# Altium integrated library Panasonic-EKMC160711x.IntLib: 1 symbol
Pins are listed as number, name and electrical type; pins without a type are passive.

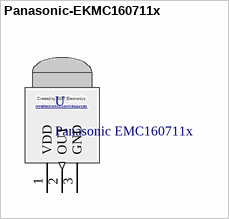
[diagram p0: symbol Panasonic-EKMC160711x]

## Panasonic-EKMC160711x
designator U, comment Panasonic EMC160711x
High sensitity and reliability Passive IR (PIR) motion detector module; Part Number: EKMC160711x; NMT Release: A210425
footprint Panasonic-EKMC160711x
pins: 1 VDD (power), 2 OUT (out), 3 GND (power)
